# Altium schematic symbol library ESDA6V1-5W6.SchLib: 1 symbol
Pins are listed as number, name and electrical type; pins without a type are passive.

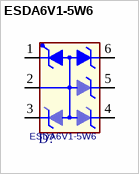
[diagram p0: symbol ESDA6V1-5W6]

## ESDA6V1-5W6
designator D?
footprint ST_SOT323-6L
pins: 1, 2, 3, 4, 5, 6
